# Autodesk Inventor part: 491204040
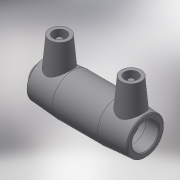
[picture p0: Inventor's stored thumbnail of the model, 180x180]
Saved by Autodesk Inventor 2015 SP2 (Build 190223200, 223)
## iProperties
Created: 2017-06
Part Number: 491204040
Material: Generic
Description: PLASSON END CAP 40
Document SubType Name: Modeling
Designer: KIM
Mass: 38.9236 g
Surface Area: 152.394 cm^2
Volume: 38.9236 cm^3
Density: 1 g/cm^3
Appearance: Default
Author: KIM
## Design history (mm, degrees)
derived "491204.ipt"
feature "Solid1::491204.ipt"
tag "TaggingFeature1"
body "Solid1"
other parameters: "d0" = 97, "d2" = 56, "d3" = 47, "d4" = 28.5, "d5" = 50.4, "d6" = 38, "d8" = 168 deg, "d10" = 18.8, "d11" = 6.26667, "d13" = 91.2, "d14" = 17.6296, "d15" = 47, "d16" = 47, "d17" = 38, "d19" = 3.52592, "d20" = 168 deg, "d22" = 52.64, "d23" = 56, "d24" = 51.0608, "d25" = 135 deg, "d26" = 41.04, "d27" = 135 deg, "d29" = 46, "d30" = 15, "d31" = 36.48, "d34" = 5 deg, "d35" = 15, "d39" = 5 deg, "d41" = 4, "d42" = 14, "d43" = 0, "d45" = 4, "d46" = 14, "d47" = 0, "d48" = 114, "d49" = 1, "d51" = 32, "d52" = 2.052, "d53" = 44, "d54" = 2.052, "d56" = 4, "d57" = 1.2, "d60" = 17.1, "d61" = 0.8, "d63" = 114, "d64" = 1, "d66" = 32, "d67" = 8, "d68" = 44, "d69" = 2.28, "d70" = 0, "d71" = 2.052, "d72" = 3, "d73" = 0, "d74" = 13.63, "d75" = 4.54333, "d76" = 3, "d77" = 0, "L_" = 114, "L_1" = 47, "D_" = 56, "A_" = 46, "d_2" = 12, "L_0" = 97, "d55" = 4
